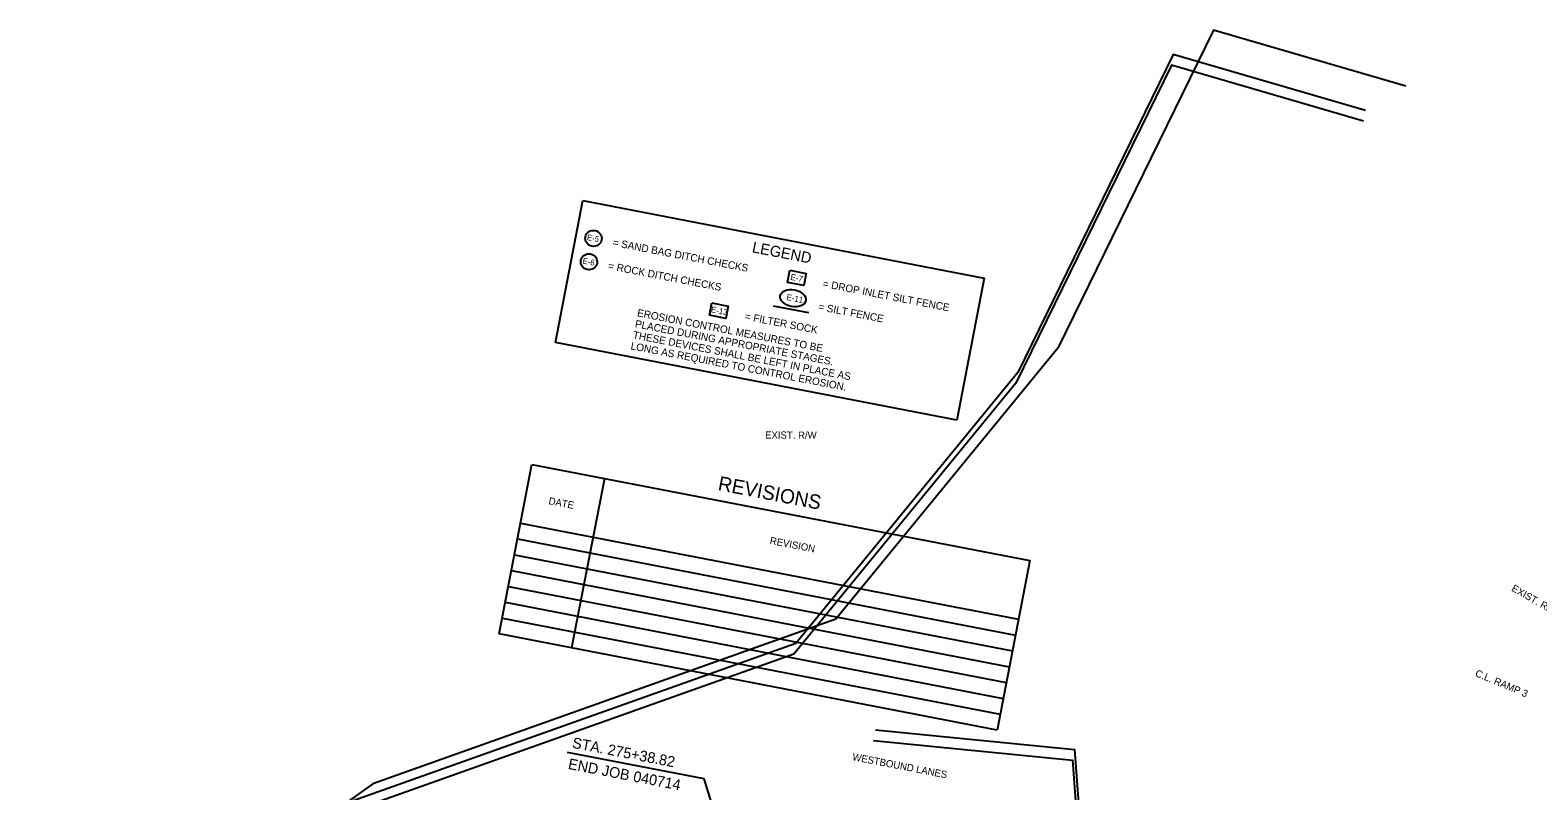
# Model space of a CAD drawing. Extents: x 605579 to 613541, y 415511 to 420599.
# Drawn here: x 609780 to 611043, y 419627 to 420265 of the extents above; entities that cross this region are included whole.
import ezdxf

# ---------------------------------------------------------------- set-up
doc = ezdxf.new("R2010")
doc.units = 0
for name, color, linetype in [('Default', 7, 'Continuous'), ('R_Curb', 7, 'Continuous'), ('R_Draft', 7, 'Continuous'), ('R_Slope Break', 7, 'Continuous'), ('R_Subgrade', 7, 'Continuous'), ('X_Phi Angle_SB', 7, 'Continuous')]:
    doc.layers.add(name, color=color, linetype=linetype)

msp = doc.modelspace()

# ---------------------------------------------------------------- linework, layer by layer
at = {"layer": 'R_Curb'}
msp.add_lwpolyline([(610402.2, 420033.9), (610431.8, 420028.2)], dxfattribs=at)
at = {"layer": 'R_Draft'}
for points in [[(610932.4, 420217.9), (610771.3, 420264.7), (610641, 419998.4)], [(610898.7, 420197.5), (610737.6, 420244.3), (610607.3, 419977.9)], [(610897.1, 420188.6), (610736, 420235.4), (610605.7, 419969.1)], [(610641, 419998.4), (610454.9, 419771.3), (610066.7, 419633.4)], [(610607.3, 419977.9), (610421.2, 419750.9), (610033, 419613)], [(610605.7, 419969.1), (610419.6, 419742), (610031.4, 419604.1)], [(610488, 419678.5), (610654.8, 419662.1), (610676.8, 419366.3)], [(610358.7, 419591.5), (610344.5, 419637.5), (610230, 419659.6)], [(610486.3, 419669.7), (610653.1, 419653.2), (610675, 419357.5)], [(610066.7, 419633.4), (609717.8, 419384.7), (608824.5, 418467.8)]]:
    msp.add_lwpolyline(points, dxfattribs=at)
at = {"layer": 'R_Slope Break'}
for p, q in [((610219.8, 420003.1), (610242.8, 420121.9)), ((610242.8, 420121.9), (610579.2, 420057)), ((610579.2, 420057), (610556.3, 419938.1)), ((610556.3, 419938.1), (610219.8, 420003.1)), ((610172.7, 419759), (610200.1, 419900.8)), ((610200.1, 419900.8), (610617.4, 419820.3)), ((610260.8, 419889.1), (610233.4, 419747.3)), ((610190.6, 419851.8), (610607.9, 419771.2)), ((610188.1, 419838.5), (610605.4, 419757.9)), ((610185.5, 419825.2), (610602.8, 419744.7)), ((610182.9, 419812), (610600.2, 419731.4)), ((610182.9, 419812), (610600.2, 419731.4)), ((610617.4, 419820.3), (610590, 419678.4)), ((610180.4, 419798.7), (610597.7, 419718.2)), ((610177.8, 419785.5), (610595.1, 419704.9)), ((610175.3, 419772.2), (610592.6, 419691.7)), ((610590, 419678.4), (610172.7, 419759))]:
    msp.add_line(p, q, dxfattribs=at)
for points in [[(610416.2, 420063.6), (610429.9, 420061), (610427.9, 420050.7), (610414.2, 420053.3)], [(610350.8, 420036.2), (610364.6, 420033.5), (610362.6, 420023.2), (610348.8, 420025.9)]]:
    msp.add_lwpolyline(points, close=True, dxfattribs=at)
for centre, major_axis, ratio in [((610251.7, 420090.3), (-6.76, 1.31), 0.97521), ((610247.9, 420070.7), (-6.76, 1.31), 0.97521), ((610418.9, 420040.2), (10.8, -2.1), 0.638788)]:
    msp.add_ellipse(centre, major_axis=major_axis, ratio=ratio, dxfattribs=at)

# ---------------------------------------------------------------- texts
at = {"layer": 'Default'}
msp.add_text('C.L. RAMP 3', height=6, rotation=337.1403, dxfattribs=at).set_placement((610990.1, 419723.8))
at = {"layer": 'R_Draft'}
for s, height, rotation, p in [('STA. 275+38.82', 9, 349.0919, (610233.3, 419663.6)), ('WESTBOUND LANES', 6, 349.0745, (610468.3, 419653.2)), ('END JOB 040714', 9, 349.0745, (610229.9, 419645.9))]:
    msp.add_text(s, height=height, rotation=rotation, dxfattribs=at).set_placement(p)
at = {"layer": 'R_Slope Break'}
for s, height, rotation, p in [('E-5', 4.88, 349.0745, (610245.9, 420089)), ('= SAND BAG DITCH CHECKS', 6.25, 349.0745, (610267.4, 420084.1)), ('LEGEND', 9.14, 349.0745, (610384.1, 420078.7)), ('E-6', 4.88, 349.0745, (610242.2, 420069.3)), ('= ROCK DITCH CHECKS', 6.25, 349.0745, (610263.6, 420064.5)), ('E-7', 5, 348.6922, (610416.4, 420055.7)), ('E-11', 5, 349.0745, (610413.1, 420038.8)), ('EROSION CONTROL MEASURES TO BE', 6.25, 349.0745, (610287.9, 420025.1)), ('E-13', 5, 348.6922, (610349.8, 420028.5)), ('THESE DEVICES SHALL BE LEFT IN PLACE AS ', 6.25, 349.0745, (610284.3, 420006.6)), ('PLACED DURING APPROPRIATE STAGES. ', 6.25, 349.0745, (610286.1, 420015.9)), ('LONG AS REQUIRED TO CONTROL EROSION.', 6.25, 349.0745, (610282.5, 419997.4)), ('REVISIONS', 12, 349.0745, (610355.4, 419879.5)), ('DATE', 6, 349.0745, (610213.7, 419867.7)), ('REVISION', 6, 349.0745, (610399.1, 419834.4))]:
    msp.add_text(s, height=height, rotation=rotation, dxfattribs=at).set_placement(p)
at = {"layer": 'R_Subgrade'}
for rotation, p in [(359.735, (610395.5, 419922.6)), (330.3043, (611020.5, 419795.4))]:
    msp.add_text('EXIST. R/W', height=6, rotation=rotation, dxfattribs=at).set_placement(p)
at = {"layer": 'X_Phi Angle_SB'}
for s, p in [('= DROP INLET SILT FENCE', (610443.4, 420049.6)), ('= FILTER SOCK', (610378.1, 420022.2)), ('= SILT FENCE', (610439.7, 420030.3))]:
    msp.add_text(s, height=6.25, rotation=349.0745, dxfattribs=at).set_placement(p)

doc.saveas('drawing.dxf')
